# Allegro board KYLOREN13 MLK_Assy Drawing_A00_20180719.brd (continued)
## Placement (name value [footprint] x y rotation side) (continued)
PR4818  5K11R2F-L1-GP  [R402H16]  59.05 70.76 90 top
PR4821  100KR2F-L1-GP  [R402H16]  53.34 82.95 0 top
PR4822  100KR2F-L1-GP  [R402H16]  51.44 82.7 180 top
PR4823  100KR2F-L1-GP  [R402H16]  47.62 75.46 180 top
PR4824  100KR2F-L1-GP  [R402H16]  47.62 79.39 0 top
PR5001  2D2R3-1-U-GP  [R603H22]  152.15 105.81 180 bottom
PR5003  3K65R2F-1-GP  [R402H16]  39.88 78.25 0 top
PR5004  0R0402-PAD-1-GP  [0R0402-PAD]  40.39 79.52 90 top
PR5101  20KR2F-L-GP  [R402H16]  153.34 21.56 90 bottom
PR5102  0R0603-PAD-1-GP-U  [0R0603-PAD-U]  154.43 26.82 0 top
PR5103  0R2J-L-GP  [R402H15]  156.84 21.99 0 bottom
PR5104  100KR2J-1-GP  [R402H16]  156.21 23.51 90 top
PR5105  1MR2J-1-GP  [R402H16]  157.61 21.99 180 bottom
PR5106  0R2J-L-GP  [R402H15]  156.08 21.1 0 bottom
PR5107  20KR2F-L-GP  [R402H16]  155.32 21.1 0 bottom
PR5114  0R0402-PAD-1-GP  [0R0402-PAD]  49.81 24.38 270 top
PR5118  0R0402-PAD-1-GP  [0R0402-PAD]  49.81 23.59 270 top
PR5125  0R0402-PAD-1-GP  [0R0402-PAD]  49.81 25.16 270 top
PR5126  0R2J-L-GP  [R402H15]  49.81 25.93 270 top
PR5127  0R0805-PAD-1-GP-U  [0R0805-PAD-U]  45.52 28.39 270 bottom
PR5201  88K7R2F-GP  [R402H16]  177.8 54.12 270 bottom
PR5202  3K16R2F-GP  [R402H16]  180.85 54.88 0 bottom
PR5203  100KR2F-L1-GP  [R402H16]  181.86 56.15 270 bottom
PR5204  10KR2F-2-DL-GP  [R402H16]  180.09 54.76 180 bottom
PR5208  100KR2J-1-GP  [R402H16]  180.59 59.33 90 bottom
PR5209  0R0402-PAD-1-GP  [0R0402-PAD]  180.59 58.57 90 bottom
PR5210  47KR2J-2-GP  [R402H16]  180.59 57.8 90 bottom
PR5301  47KR2J-2-GP  [R402H16]  37.21 23.26 90 bottom
PR5302  100KR2F-L1-GP  [R402H16]  37.03 18.08 270 bottom
PR5303  16K9R2F-GP  [R402H16]  46.99 19.2 0 bottom
PR5304  13K3R2F-L1-GP  [R402H16]  47.37 20.47 90 bottom
PR5306  0R0402-PAD-1-GP  [0R0402-PAD]  37.21 24.02 270 bottom
PR5308  0R0402-PAD-1-GP  [0R0402-PAD]  37.03 17.29 270 bottom
PR5309  47KR2J-2-GP  [R402H16]  129.16 15.51 180 bottom
PR5310  10KR2F-2-DL-GP  [R402H16]  140.21 21.48 270 bottom
PR5317  0R0402-PAD-1-GP  [0R0402-PAD]  128.4 15.51 0 bottom
PR5319  29K4R2F-GP  [R402H16]  137.03 28.85 180 bottom
PR5320  13K7R2F-GP  [R402H16]  136.27 28.85 0 bottom
PR5321  0R0805-PAD-1-GP-U  [0R0805-PAD-U]  137.41 30.75 90 bottom
PR5322  0R0805-PAD-1-GP-U  [0R0805-PAD-U]  48.51 16.91 180 bottom
PT4701  SE330U2VDM-4-GP  [CT7343H83]  74.3 62.76 180 bottom
PT4702  ST33U25VDM-5-GP  [CT7343H79]  62.48 67.07 270 bottom
PT4801  SE330U2VDM-4-GP  [CT7343H83]  74.22 84.3 0 bottom
PT4803  SE330U2VDM-4-GP  [CT7343H83]  74.22 76.17 180 bottom
PT4805  SE33U25VM-11-GP  [CT7343H83]  54.1 55.64 270 bottom
PT4807  ST33U25VDM-5-GP  [CT7343H79]  52.83 78.12 90 bottom
PU4301  AON7403-GP-U  [PPAK-8P-3232H36]  32.38 73.04 0 bottom
PU4302  AON7403-GP-U  [PPAK-8P-3232H36]  32.38 70.25 180 bottom
PU4401  ISL9538HRTZ-GP-U  [QFN32J4-G2D85H34]  35.05 46.25 270 top
PU4403  AON7380-GP  [PPAK-8P-3232H36]  40.64 61.99 90 top
PU4404  AON7380-GP  [PPAK-8P-3232H36]  41.4 58.69 0 top
PU4405  AON7380-GP  [PPAK-8P-3232H36]  48.9 57.93 270 top
PU4406  AON7380-GP  [PPAK-8P-3232H36]  48.13 61.23 180 top
PU4412  AON7401-GP  [PPAK-8P-3232H36]  146.05 17.54 90 bottom
PU4501  SY8286BRAC-GP  [QFN20Z3-G1D1H36]  126.47 21.23 180 bottom
PU4502  SY8288CRAC-GP  [QFN20Z3-G1D1H36]  63.5 20.85 0 bottom
PU4601  ISL95859CHRTZ-T-1-GP  [QFN40J5-G3D6-DIFF-H34]  44.58 75.96 90 bottom
PU4701  AOZ5038QI-05-GP  [QFN31G5-G4P-9H34]  60.2 61.74 270 bottom
PU4801  AOZ5038QI-05-GP  [QFN31G5-G4P-9H34]  60.2 82.31 270 bottom
PU4802  AOZ5038QI-05-GP  [QFN31G5-G4P-9H34]  60.2 73.17 270 bottom
PU5001  ISL95808HRZ-T-1-GP  [DFN8G2-G1710-U1H40]  151.38 102.63 90 bottom
PU5002  AON7408-GP  [PPAK-8P-3232H36]  143.89 106.7 90 bottom
PU5003  AON7408-GP  [PPAK-8P-3232H36]  142.62 102.89 270 bottom
PU5101  SY8288RAC-GP  [QFN20Z3-G1H36]  154.56 25.04 180 bottom
PU5102  APL5338XAI-TRG-GP  [MSOP10-G2D5H44]  45.54 25.62 90 bottom
PU5201  AOZ2262QI-10-GP-U  [QFN22G4-G2PH42]  176.28 56.91 90 bottom
PU5301  APL5934KAI-TRG-GP-U  [SOIC8-G3530H63]  42.67 18.81 270 bottom
PU5303  APL5934KAI-TRG-GP-U  [SOIC8-G3530H63]  136.14 24.41 0 bottom
Q401  2N7002KDW-1-GP  [SOT-363H44]  160.53 86.51 180 bottom
Q501  PJA138KA-GP  [SOT23DGS2D4H44]  85.47 61.36 0 bottom
Q502  2N7002K-2-GP  [SOT23DGS2D4H44]  85.6 57.93 0 bottom
Q1701  PJT138KA-GP  [SOT-363H44]  144.4 51.33 90 bottom
Q1702  2N7002KDW-1-GP  [SOT-363H44]  132.53 51.74 270 bottom
Q1802  2N7002K-2-GP  [SOT23DGS2D4H44]  156.31 47.9 270 bottom
Q2001  PJT138KA-GP  [SOT-363H44]  183.77 48.91 0 top
Q2408  2N7002K-2-GP  [SOT23DGS2D4H44]  104.9 14.88 0 bottom
Q2414  2N7002K-2-GP  [SOT23DGS2D4H44]  68.17 14.62 270 bottom
Q2416  2N7002KDW-1-GP  [SOT-363H44]  124.97 11.04 270 bottom
Q2417  2N7002KDW-1-GP  [SOT-363H44]  107.82 11.45 180 bottom
Q2505  2N7002K-2-GP  [SOT23DGS2D4H44]  150.93 77.23 270 bottom
Q2507  PJA3415-GP  [SOT23DGS2D4H44]  155.07 52.09 180 bottom
Q2510  2N7002K-2-GP  [SOT23DGS2D4H44]  151.51 52.09 180 bottom
Q2601  2N7002KDW-1-GP  [SOT-363H44]  46.23 13.48 270 bottom
Q2602  2N7002K-2-GP  [SOT23DGS2D4H44]  145.54 97.81 180 bottom
Q2603  MMBT3904-5-GP-U  [SOT23CBE2D4H46-U]  48.77 68.73 180 bottom
Q4001  2N7002K-2-GP  [SOT23DGS2D4H44]  33.86 18.71 180 bottom
Q4002  PJA3415-GP  [SOT23DGS2D4H44]  30.12 20.39 0 bottom
Q4301  PJA138KA-GP  [SOT23DGS2D4H44]  53.95 13.58 180 bottom
Q4302  MMBT3904-5-GP-U  [SOT23CBE2D4H46-U]  57.43 13.78 180 bottom
Q4304  LMUN5212T1G-GP  [SOT323CBE2D2H40]  35.69 80.66 180 bottom
Q4305  LTA024EUB-FS8-GP  [SC70-2D2-312H44]  33.15 80.66 180 bottom
Q4348  PJA3415-GP  [SOT23DGS2D4H44]  31.65 25.52 90 bottom
Q4349  2N7002KDW-1-GP  [SOT-363H44]  28.52 25.16 180 bottom
Q5705  2N7002KDW-1-GP  [SOT-363H44]  15.88 59.45 180 bottom
Q6101  PJA3415-GP  [SOT23DGS2D4H44]  182.63 41.67 180 top
Q6102  2N7002K-2-GP  [SOT23DGS2D4H44]  182.63 44.21 180 top
Q6401  RN2418-GP  [SOT23CBE2D6H62]  116.71 15.13 270 bottom
Q6402  RN2418-GP  [SOT23CBE2D6H62]  120.02 15.13 270 bottom
Q6403  PJA138KA-GP  [SOT23DGS2D4H44]  123.95 14.75 0 bottom
Q6404  PJT138KA-GP  [SOT-363H44]  121.46 10.91 90 bottom
Q6501  PJA3402-R1-00001-GP  [SOT23DGS2D4H44]  74.8 15.89 180 bottom
Q6502  PJA3415-GP  [SOT23DGS2D4H44]  128.27 9.7 0 bottom
Q6503  2N7002K-2-GP  [SOT23DGS2D4H44]  131.7 9.7 0 bottom
Q6504  2N7002KDW-1-GP  [SOT-363H44]  139.45 11.07 270 bottom
Q6505  RN2418-GP  [SOT23CBE2D6H62]  64.9 13.61 270 bottom
Q7401  PJA3415-GP  [SOT23DGS2D4H44]  21.97 65.8 0 bottom
Q7402  PJT138KA-GP  [SOT-363H44]  18.8 66.31 270 bottom
Q7404  2N7002KDW-1-GP  [SOT-363H44]  17.65 69.74 0 bottom
Q7405  2N7002KDW-1-GP  [SOT-363H44]  20.19 69.74 0 bottom
Q7406  PJT138KA-GP  [SOT-363H44]  15.11 68.73 0 bottom
R301  1KR2J-1-GP  [R402H16]  95 95.9 0 bottom
R302  499R2F-2-GP  [R402H16]  96.27 96.28 270 bottom
R303  100KR2J-1-GP  [R402H16]  130.68 61.54 90 bottom
R304  49D9R2F-GP  [R402H16]  124.33 73.04 180 top
R305  49D9R2F-GP  [R402H16]  126.69 74.47 270 top
R308  1KR2J-1-GP  [R402H16]  115.32 95.4 270 bottom
R310  51R2J-2-GP  [R402H16]  94.58 94.11 0 bottom
R317  51R2J-2-GP  [R402H16]  96.39 88.13 270 top
R401  24D9R2F-L-GP  [R402H16]  108.5 85.24 90 top
R402  10KR2J-3-GP  [R402H16]  149.86 90.44 270 top
R403  100KR2J-1-GP  [R402H16]  131.67 86.41 0 top
R404  0R2J-L-GP  [R402H15]  161.04 88.54 90 bottom
R405  10KR2J-3-GP  [R402H16]  162.31 86.51 0 bottom
R406  10KR2J-3-GP  [R402H16]  160.4 84.47 90 bottom
R501  121R2F-GP  [R402H16]  123.72 74.68 180 top
R502  80D6R2F-L-GP  [R402H16]  122.95 74.68 180 top
R503  100R2F-L1-GP-U  [R402H14]  122.19 74.68 180 top
R504  0R0402-PAD-2-GP  [0R0402-PAD-1]  135.2 57.73 90 top
R505  470R2F-GP  [R402H16]  134.62 56.41 180 top
R506  10KR2F-2-DL-GP  [R402H16]  84.07 59.96 270 bottom
R507  10KR2F-2-DL-GP  [R402H16]  83.31 58.31 180 bottom
R601  49D9R2F-GP  [R402H16]  103.4 88.69 0 top
R709  0R0402-PAD-2-GP  [0R0402-PAD-1]  91.82 96.28 90 bottom
R719  100R2F-L1-GP-U  [R402H14]  110.94 86.56 270 top
R720  100R2F-L1-GP-U  [R402H14]  110.79 87.91 270 top
R723  54D9R2F-L1-GP  [R402H16]  88.77 95.14 90 bottom
R726  100R2F-L1-GP-U  [R402H14]  91.82 97.05 270 bottom
R727  56R2F-1-GP  [R402H16]  89.53 96.79 90 bottom
R728  220R2F-GP  [R402H16]  90.04 97.55 90 bottom
R732  0R0402-PAD-2-GP  [0R0402-PAD-1]  88.27 96.41 180 bottom
R807  100R2F-L1-GP-U  [R402H14]  94.61 88.28 270 top
R808  100R2F-L1-GP-U  [R402H14]  92.96 88.28 90 top
R809  100R2F-L1-GP-U  [R402H14]  117.52 86.51 270 top
R810  100R2F-L1-GP-U  [R402H14]  118.92 85.24 270 top
R811  D0002R5J-2-GP  [R805H16]  105.54 82.82 270 top
R812  D0002R5J-2-GP  [R805H16]  102.36 82.82 270 top
R813  D0002R5J-2-GP  [R805H16]  105.54 80.92 270 top
R814  D0002R5J-2-GP  [R805H16]  105.54 79.01 270 top
R815  D0002R5J-2-GP  [R805H16]  102.36 80.92 270 top
R1103  0R0603-PAD-2-GP-U  [0R0603-PAD-1-U]  137.08 75.44 270 top
R1104  0R0603-PAD-2-GP-U  [0R0603-PAD-1-U]  150.41 77.62 270 top
R1201  240R2D-GP  [R402H16]  50.23 41.17 270 top
R1202  2D7R2F-1-GP  [R402H16]  94.66 34.95 90 top
R1203  24D9R2F-L-GP  [R402H16]  92.5 34.19 270 top
R1204  240R2D-GP  [R402H16]  59.73 41.17 270 top
R1205  240R2D-GP  [R402H16]  80.03 41.17 270 top
R1208  49D9R2F-GP  [R402H16]  52.11 33.68 90 top
R1211  36R2F-1-GP  [R402H16]  44.49 38.89 270 top
R1212  240R2F-1-GP  [R402H16]  50.68 42.4 180 top
R1213  240R2F-1-GP  [R402H16]  60.18 42.4 180 top
R1214  240R2F-1-GP  [R402H16]  80.48 42.4 180 top
R1215  240R2F-1-GP  [R402H16]  70.33 42.4 180 top
R1220  0R2J-L-GP  [R402H15]  93.13 38.13 180 bottom
R1221  0R2J-L-GP  [R402H15]  91.57 37.1 0 bottom
R1222  1K8R2F-GP  [R402H16]  92.63 35.46 0 top
R1223  1K8R2F-GP  [R402H16]  93.39 35.46 0 top
R1224  36R2F-1-GP  [R402H16]  47.92 36.47 270 top
R1225  33R2F-3-GP  [R402H16]  47.92 39.78 270 top
R1226  33R2F-3-GP  [R402H16]  47.92 40.54 270 top
R1234  240R2D-GP  [R402H16]  69.88 41.17 270 top
R1301  240R2D-GP  [R402H16]  101.64 40.79 180 bottom
R1302  2D7R2F-1-GP  [R402H16]  99.68 33.78 270 top
R1303  24D9R2F-L-GP  [R402H16]  100.46 35.32 180 top
R1304  240R2D-GP  [R402H16]  112.22 41.17 270 top
R1305  240R2D-GP  [R402H16]  122.37 41.15 270 top
R1306  240R2D-GP  [R402H16]  132.52 41.17 270 top
R1311  36R2F-1-GP  [R402H16]  145.92 39.64 270 top
R1312  36R2F-1-GP  [R402H16]  145.46 37.24 270 bottom
R1313  33R2F-3-GP  [R402H16]  145.38 41.03 270 bottom
R1314  33R2F-3-GP  [R402H16]  145.38 41.82 270 bottom
R1320  1K8R2F-GP  [R402H16]  99.68 32.26 90 top
R1321  1K8R2F-GP  [R402H16]  99.68 33.02 90 top
R1330  49D9R2F-GP  [R402H16]  135.25 34.06 0 top
R1331  240R2F-1-GP  [R402H16]  101.64 42.57 0 bottom
R1332  240R2F-1-GP  [R402H16]  113.32 42.4 180 top
R1333  240R2F-1-GP  [R402H16]  123.47 42.38 180 top
R1334  240R2F-1-GP  [R402H16]  133.61 42.4 180 top
R1339  0R2J-L-GP  [R402H15]  101.6 37.86 180 bottom
R1340  0R2J-L-GP  [R402H15]  143.76 37.99 90 top
R1501  20KR2J-L2-GP  [R402H16]  150.37 59.45 180 bottom
R1502  1KR2J-1-GP  [R402H16]  140.97 75.33 270 bottom
R1503  1KR2J-1-GP  [R402H16]  142.75 74.57 270 bottom
R1504  4K7R2J-2-GP  [R402H16]  134.75 80.41 0 top
R1505  20KR2J-L2-GP  [R402H16]  133.41 79.86 270 top
R1506  100KR2F-L1-GP  [R402H16]  132.23 63.48 0 bottom
R1507  1KR2J-1-GP  [R402H16]  133.01 63.48 180 bottom
R1508  100KR2F-L1-GP  [R402H16]  137.03 62.5 90 bottom
R1509  4K7R2J-2-GP  [R402H16]  137.03 63.39 270 bottom
R1510  100KR2F-L1-GP  [R402H16]  140.59 60.72 90 top
R1511  4K7R2J-2-GP  [R402H16]  142.24 60.72 90 top
R1512  4K7R2J-2-GP  [R402H16]  120.9 60.09 0 bottom
R1515  20KR2J-L2-GP  [R402H16]  150.5 58.06 90 top
R1516  4K7R2J-2-GP  [R402H16]  151.76 57.04 0 top
R1517  1KR2J-1-GP  [R402H16]  93.82 94.11 0 bottom
R1518  1KR2J-1-GP  [R402H16]  87.12 90.7 180 bottom
R1519  4K7R2J-2-GP  [R402H16]  149.86 70.5 0 top
R1520  4K7R2J-2-GP  [R402H16]  149.73 72.28 270 top
R1521  10KR2J-3-GP  [R402H16]  150.88 75.08 270 bottom
R1522  4K7R2J-2-GP  [R402H16]  138.46 76.93 180 top
R1523  20KR2J-L2-GP  [R402H16]  139.24 76.93 0 top
R1524  100KR2F-L1-GP  [R402H16]  139.06 55.01 180 top
R1525  20KR2J-L2-GP  [R402H16]  136.91 56.66 0 top
R1526  4K7R2J-2-GP  [R402H16]  153.97 71.16 180 top
R1527  1KR2J-1-GP  [R402H16]  140.97 73.55 270 bottom
R1528  4K7R2J-2-GP  [R402H16]  153.97 69.56 180 top
R1551  4K7R2J-2-GP  [R402H16]  135.51 80.41 0 top
R1552  20KR2J-L2-GP  [R402H16]  153.67 81.17 180 top
R1553  20KR2J-L2-GP  [R402H16]  150.5 61.23 180 top
R1554  20KR2J-L2-GP  [R402H16]  149.61 74.82 0 bottom
R1555  20KR2J-L2-GP  [R402H16]  136.4 60.47 270 top
R1601  0R2J-L-GP  [R402H15]  129.03 85.87 180 top
R1602  0R2J-L-GP  [R402H15]  132.72 89.05 90 top
R1603  113R2F-GP  [R402H16]  128.97 87.1 90 top
R1604  100R2F-L1-GP-U  [R402H14]  130.71 87.95 90 top
R1606  10KR2J-3-GP  [R402H16]  149.86 91.33 90 top
R1608  10KR2J-3-GP  [R402H16]  149.86 89.68 90 top
R1701  10KR2J-3-GP  [R402H16]  154.43 88.28 270 top
R1702  1KR2J-1-GP  [R402H16]  129.13 51.84 90 bottom
R1703  10KR2J-3-GP  [R402H16]  125.48 63.26 0 bottom
R1704  0R0402-PAD-2-GP  [0R0402-PAD-1]  130.68 51.77 0 bottom
R1706  0R0402-PAD-2-GP  [0R0402-PAD-1]  123.19 58.82 0 bottom
R1707  10KR2J-3-GP  [R402H16]  125.19 74.07 0 top
R1708  0R2J-L-GP  [R402H15]  127.51 55.52 180 bottom
R1713  0R0402-PAD-2-GP  [0R0402-PAD-1]  137.79 55.21 180 top
R1714  10KR2J-3-GP  [R402H16]  111.89 94.13 270 bottom
R1715  100KR2J-1-GP  [R402H16]  136.55 54.45 270 top
R1716  100KR2F-L1-GP  [R402H16]  159.64 81.3 180 bottom
R1717  10KR2J-3-GP  [R402H16]  160.4 83.33 270 bottom
R1718  100KR2F-L1-GP  [R402H16]  158.62 80.66 0 bottom
R1719  47KR2F-GP  [R402H16]  157.73 80.66 180 bottom
R1721  10KR2J-3-GP  [R402H16]  127 60.22 180 bottom
R1722  10KR2J-3-GP  [R402H16]  127.89 60.22 180 bottom
R1726  10KR2J-3-GP  [R402H16]  141.35 51.83 180 bottom
R1727  100KR2J-1-GP  [R402H16]  146.43 51.45 180 bottom
R1728  0R0402-PAD-2-GP  [0R0402-PAD-1]  147.45 51.45 0 bottom
R1730  330KR2J-L1-GP  [R402H16]  143.89 51.2 180 top
R1731  100KR2F-L1-GP  [R402H16]  128.29 74.78 0 top
R1737  100KR2J-1-GP  [R402H16]  134.41 52.6 180 bottom
R1738  10KR2J-3-GP  [R402H16]  126.75 55.52 0 bottom
R1801  150KR2J-GP  [R402H16]  137.92 59.71 180 top
R1803  60D4R2F-GP  [R402H16]  132.76 94.51 0 bottom
R1805  33R2F-3-GP  [R402H16]  127.25 60.22 0 top
R1815  10MR2J-L-GP  [R402H16]  123.44 58.32 90 top
R1816  10KR2J-3-GP  [R402H16]  158.39 48.76 180 bottom
R1818  8K2R2F-1-GP  [R402H16]  131.57 55.9 90 top
R1820  10KR2J-3-GP  [R402H16]  131.57 56.66 270 top
R1821  10KR2J-3-GP  [R402H16]  128.14 60.22 180 top
R1839  0R2J-L-GP  [R402H15]  135.04 93.83 0 bottom
R1840  0R2J-L-GP  [R402H15]  134.28 93.83 0 bottom
R1841  1MR2J-1-GP  [R402H16]  134.66 95.05 90 bottom
R1901  200R2F-L-GP  [R402H16]  134.24 71.9 180 top
R1908  0R0402-PAD-2-GP  [0R0402-PAD-1]  122.43 60.09 0 bottom
R1909  1KR2J-1-GP  [R402H16]  119.38 60.09 0 bottom
R1910  10KR2J-3-GP  [R402H16]  142.75 72.79 90 bottom
R1911  10KR2J-3-GP  [R402H16]  142.75 73.55 270 bottom
R1920  0R0402-PAD-2-GP  [0R0402-PAD-1]  121.67 60.09 0 bottom
R1921  0R0402-PAD-2-GP  [0R0402-PAD-1]  120.14 60.09 0 bottom
R2001  0R2J-L-GP  [R402H15]  130.53 59.2 180 bottom
R2002  0R2J-L-GP  [R402H15]  131.29 59.2 180 bottom
R2003  10KR2F-2-DL-GP  [R402H16]  183.64 51.58 0 top
R2004  10KR2J-3-GP  [R402H16]  182.47 51.66 270 top
R2005  10KR2J-3-GP  [R402H16]  149.86 87.39 90 top
R2008  10KR2J-3-GP  [R402H16]  152.4 86.76 90 top
R2009  10KR2J-3-GP  [R402H16]  149.37 84.99 0 top
R2010  10KR2J-3-GP  [R402H16]  150.16 84.99 180 top
R2011  10KR2J-3-GP  [R402H16]  148.21 73.81 90 bottom
R2012  10KR2J-3-GP  [R402H16]  145.08 73.03 90 bottom
R2013  10KR2J-3-GP  [R402H16]  148.56 71.96 90 bottom
R2014  10KR2J-3-GP  [R402H16]  146.88 71.96 90 bottom
R2015  10KR2J-3-GP  [R402H16]  145.1 76.18 90 bottom
R2016  10KR2J-3-GP  [R402H16]  148.21 76.85 90 bottom
R2017  10KR2J-3-GP  [R402H16]  145.1 75.39 90 bottom
R2018  10KR2J-3-GP  [R402H16]  148.21 76.09 90 bottom
R2020  0R2J-L-GP  [R402H15]  150.11 79.52 90 top
R2021  0R2J-L-GP  [R402H15]  150.11 78.76 90 top
R2022  10KR2J-3-GP  [R402H16]  145.1 74.6 90 bottom
R2027  0R2J-L-GP  [R402H15]  147.32 58.69 180 top
R2028  0R2J-L-GP  [R402H15]  129.7 54.57 270 bottom
R2029  10KR2J-3-GP  [R402H16]  148.21 75.33 90 bottom
R2030  10KR2J-3-GP  [R402H16]  146.81 72.92 90 bottom
R2031  10KR2J-3-GP  [R402H16]  148.59 72.92 90 bottom
R2032  10KR2J-3-GP  [R402H16]  145.1 73.79 90 bottom
R2033  10KR2J-3-GP  [R402H16]  148.21 74.57 90 bottom
R2034  10KR2J-3-GP  [R402H16]  149.35 74.69 180 top
R2035  10KR2J-3-GP  [R402H16]  150.11 74.69 0 top
R2037  10KR2J-3-GP  [R402H16]  142.75 75.33 270 bottom
R2038  10KR2J-3-GP  [R402H16]  151.64 74.69 0 top
R2041  10KR2J-3-GP  [R402H16]  137.23 82.6 90 top
R2043  10KR2J-3-GP  [R402H16]  131.55 57.5 270 top
R2044  10KR2J-3-GP  [R402H16]  139.32 83.58 0 top
R2045  10KR2J-3-GP  [R402H16]  149.86 86.25 270 top
R2046  10KR2J-3-GP  [R402H16]  150.88 74.69 0 top
R2048  51KR2J-1-GP  [R402H16]  151.64 83.89 90 top
R2049  51KR2J-1-GP  [R402H16]  152.4 74.69 0 top
R2050  10KR2J-3-GP  [R402H16]  185.04 47.01 270 top
R2051  10KR2J-3-GP  [R402H16]  129.13 52.97 90 bottom
R2052  10KR2J-3-GP  [R402H16]  129.7 53.79 90 bottom
R2053  10KR2J-3-GP  [R402H16]  133.46 57.78 90 top
R2101  150R2F-1-GP  [R402H16]  135.58 72.24 90 top
R2102  0R2J-L-GP  [R402H15]  160.78 96.16 0 top
R2107  10KR2J-3-GP  [R402H16]  137.66 76.94 0 top
R2108  200R2F-L-GP  [R402H16]  133.39 80.8 270 top
R2109  10KR2J-3-GP  [R402H16]  151.66 85.42 90 top
R2110  10KR2J-3-GP  [R402H16]  151.66 84.66 90 top
R2111  10KR2J-3-GP  [R402H16]  155.06 80.65 90 bottom
R2112  10KR2J-3-GP  [R402H16]  155.06 81.56 270 bottom
R2113  10KR2J-3-GP  [R402H16]  134.92 76.35 270 top
R2114  10KR2J-3-GP  [R402H16]  134.92 75.57 270 top
R2115  10KR2J-3-GP  [R402H16]  155.57 79.22 90 bottom
R2116  10KR2J-3-GP  [R402H16]  157.35 79.21 270 bottom
R2117  10KR2J-3-GP  [R402H16]  130.98 79.5 90 top
R2118  10KR2J-3-GP  [R402H16]  130.88 81.66 180 top
R2119  0R0402-PAD-2-GP  [0R0402-PAD-1]  140.97 72.79 270 bottom
R2202  0R0603-PAD-2-GP-U  [0R0603-PAD-1-U]  142.49 97.3 90 bottom
R2203  0R0603-PAD-2-GP-U  [0R0603-PAD-1-U]  151.51 81.3 180 top
R2204  0R0603-PAD-2-GP-U  [0R0603-PAD-1-U]  148.72 59.07 180 top
R2205  0R0603-PAD-2-GP-U  [0R0603-PAD-1-U]  124.89 98.44 270 bottom
R2401  0R0402-PAD-2-GP  [0R0402-PAD-1]  19.41 31.79 270 bottom
R2402  0R0402-PAD-2-GP  [0R0402-PAD-1]  104.39 9.67 90 bottom
R2403  0R2J-L-GP  [R402H15]  106.55 17.67 180 bottom
R2404  0R2J-L-GP  [R402H15]  108.23 8.6 270 bottom
R2405  0R2J-L-GP  [R402H15]  186.33 43.6 0 top
R2406  10KR2J-3-GP  [R402H16]  108.23 7.84 270 bottom
R2407  100KR2J-1-GP  [R402H16]  82.37 9.37 0 bottom
R2410  0R2J-L-GP  [R402H15]  95.12 23.13 90 bottom
R2414  10KR2J-3-GP  [R402H16]  96.39 4.72 90 top
R2415  10KR2J-3-GP  [R402H16]  87.12 19.8 90 top
R2416  10KR2J-3-GP  [R402H16]  20.83 32.53 0 bottom
R2417  100KR2J-1-GP  [R402H16]  102.23 14.62 270 bottom
R2418  0R2J-L-GP  [R402H15]  102.23 15.39 270 bottom
R2421  330R2J-3-GP  [R402H16]  90.55 5.35 270 top
R2423  330R2J-3-GP  [R402H16]  90.07 6.52 180 top
R2424  20KR2F-L-GP  [R402H16]  83.95 16.91 90 top
R2430  10KR2J-3-GP  [R402H16]  87.88 24.02 90 bottom
R2432  1KR2J-1-GP  [R402H16]  84.45 6.62 0 top
R2434  100KR2J-1-GP  [R402H16]  80.64 12.85 90 top
R2437  43R2J-GP  [R402H16]  104.39 10.43 270 bottom
R2440  0R0402-PAD-2-GP  [0R0402-PAD-1]  103.25 17.67 180 bottom
R2441  100KR2F-L1-GP  [R402H16]  94.61 6.24 270 top
R2442  27KR2F-L-GP  [R402H16]  96.39 6.24 270 top
R2443  37K4R2F-1-GP  [R402H16]  92.94 5.48 270 top
R2444  100KR2F-L1-GP  [R402H16]  92.94 6.24 90 top
R2445  0R0402-PAD-2-GP  [0R0402-PAD-1]  92.2 8.78 270 top
R2446  0R0603-PAD-2-GP-U  [0R0603-PAD-1-U]  80.77 13.99 90 top
R2447  0R0402-PAD-2-GP  [0R0402-PAD-1]  80.26 12.46 90 bottom
R2448  10KR2F-2-DL-GP  [R402H16]  84.33 18.18 180 top
R2451  100KR2J-1-GP  [R402H16]  85.22 6.62 180 top
R2452  100KR2J-1-GP  [R402H16]  63.12 3.37 0 top
R2453  100KR2J-1-GP  [R402H16]  64.14 3.37 0 top
R2454  100KR2J-1-GP  [R402H16]  88.11 6.24 90 top
R2455  100KR2J-1-GP  [R402H16]  105.03 17.67 180 bottom
R2456  100KR2J-1-GP  [R402H16]  96.39 23.54 0 bottom
R2459  0R0402-PAD-2-GP  [0R0402-PAD-1]  80.26 13.23 90 bottom
R2461  0R2J-L-GP  [R402H15]  82.04 5.61 270 bottom
R2462  0R0402-PAD-2-GP  [0R0402-PAD-1]  95.12 23.89 90 bottom
R2463  1KR2J-1-GP  [R402H16]  88.11 7 270 top
R2465  10KR2F-2-DL-GP  [R402H16]  83.69 19.96 90 top
R2467  0R0402-PAD-2-GP  [0R0402-PAD-1]  105.28 11.96 0 bottom
R2468  0R0402-PAD-2-GP  [0R0402-PAD-1]  109.55 12.57 180 bottom
R2472  0R2J-L-GP  [R402H15]  88.49 7.89 90 top
R2473  0R0402-PAD-2-GP  [0R0402-PAD-1]  88.01 8.65 90 top
R2480  100KR2J-1-GP  [R402H16]  99.34 13.2 270 top
R2489  100KR2J-1-GP  [R402H16]  68.2 11.45 180 bottom
R2494  0R2J-L-GP  [R402H15]  92.58 4.21 0 top
R2495  0R2J-L-GP  [R402H15]  124.71 12.72 90 bottom
R2496  100KR2J-1-GP  [R402H16]  90.35 25.55 270 bottom
R2497  100KR2J-1-GP  [R402H16]  86.23 8.65 90 top
R2498  0R2J-L-GP  [R402H15]  124.71 9.16 90 bottom
R2503  15R2F-2-GP  [R402H16]  141.48 59.96 270 top
R2504  10MR2J-L-GP  [R402H16]  152.78 75.33 90 bottom
R2505  0R2J-L-GP  [R402H15]  156.97 76.22 90 bottom
R2506  33R2F-3-GP  [R402H16]  134.61 57.99 270 bottom
R2507  33R2F-3-GP  [R402H16]  137.16 59.94 180 bottom
R2508  33R2F-3-GP  [R402H16]  135.89 60.57 0 bottom
R2509  33R2F-3-GP  [R402H16]  133.8 63.48 0 bottom
R2511  4K7R2J-2-GP  [R402H16]  151.26 54.63 0 bottom
R2512  0R2J-L-GP  [R402H15]  153.16 53.61 270 bottom
R2513  0R2J-L-GP  [R402H15]  160.55 74.54 90 bottom
R2514  10KR2J-3-GP  [R402H16]  155.91 73.54 0 bottom
R2516  0R0603-PAD-2-GP-U  [0R0603-PAD-1-U]  151.05 73.26 0 bottom
R2517  47KR2F-GP  [R402H16]  156.97 75.33 270 bottom
R2518  100KR2J-1-GP  [R402H16]  159.66 49.22 270 bottom
R2519  4K7R2J-2-GP  [R402H16]  139.19 62.12 180 bottom
R2520  100KR2J-1-GP  [R402H16]  156.67 73.54 0 bottom
R2522  0R5J-5-GP  [R805H24]  156.34 71.14 180 bottom
R2567  1MR2J-1-GP  [R402H16]  160.22 50.49 0 bottom
R2601  0R2J-L-GP  [R402H15]  147.32 97.68 90 top
R2602  0R0402-PAD-2-GP  [0R0402-PAD-1]  148.59 97.3 0 top
R2603  7K5R2F-1-GP  [R402H16]  151.26 49.29 270 bottom
R2604  7K5R2F-1-GP  [R402H16]  145.54 98.19 90 top
R2607  10KR2J-3-GP  [R402H16]  155.7 98.19 0 top
R2608  27KR2F-L-GP  [R402H16]  62.36 55.39 270 bottom
R2609  10R2F-L-GP  [R402H14]  93.34 4.21 0 top
R2610  NTC-100K-8-GP  [NTC-603H38]  63.5 56.53 270 bottom
R2611  0R0402-PAD-2-GP  [0R0402-PAD-1]  92.58 2.43 180 top
R2612  0R0402-PAD-2-GP  [0R0402-PAD-1]  169.8 83.08 180 bottom
R2613  0R0402-PAD-2-GP  [0R0402-PAD-1]  165.28 80.31 270 bottom
R2614  0R0402-PAD-2-GP  [0R0402-PAD-1]  165.28 79.55 270 bottom
R2615  0R2J-L-GP  [R402H15]  149.35 97.3 0 top
R2616  0R2J-L-GP  [R402H15]  151.26 96.41 270 top
R2705  0R0603-PAD-2-GP-U  [0R0603-PAD-1-U]  20.85 11.45 0 top
R2707  0R0805-PAD-2-GP-U  [0R0805-PAD-1-U]  25.15 11.07 180 top
R2712  0R0805-PAD-2-GP-U  [0R0805-PAD-1-U]  23.33 11.05 180 top
R2721  0R0402-PAD-2-GP  [0R0402-PAD-1]  29.46 18.05 270 top
R2724  0R0603-PAD-2-GP-U  [0R0603-PAD-1-U]  21.97 25.42 0 top
R2728  0R2J-L-GP  [R402H15]  17.4 18.18 90 top
R2730  33R2F-3-GP  [R402H16]  26.19 24.91 0 top
R2738  0R0402-PAD-2-GP  [0R0402-PAD-1]  29.46 17.16 270 top
R2739  0R0805-PAD-2-GP-U  [0R0805-PAD-1-U]  21.84 15.89 0 bottom
R2741  200KR2F-L-GP  [R402H16]  29.59 12.97 90 top
R2742  100KR2J-1-GP  [R402H16]  32 14.24 0 top
R2743  10KR2J-3-GP  [R402H16]  30.73 15.39 0 top
R2744  100KR2J-1-GP  [R402H16]  27.81 13.23 180 top
R2745  2K2R2J-2-GP  [R402H16]  9.4 7.26 180 bottom
R2746  0R2J-L-GP  [R402H15]  28.7 24.53 0 top
R2747  100KR2J-1-GP  [R402H16]  19.56 12.72 0 top
R2748  0R3J-0-U-GP  [R603H22]  26.04 18.56 180 bottom
R2749  0R0603-PAD-2-GP-U  [0R0603-PAD-1-U]  32 16.4 0 top
R2750  0R3J-0-U-GP  [R603H22]  26.04 20.97 0 bottom
R2751  0R0603-PAD-2-GP-U  [0R0603-PAD-1-U]  23.62 27.58 0 top
R2754  0R0402-PAD-2-GP  [0R0402-PAD-1]  17.4 17.42 90 top
R2905  0R0402-PAD-2-GP  [0R0402-PAD-1]  17.53 26.56 180 top
R2907  0R0402-PAD-2-GP  [0R0402-PAD-1]  17.4 21.23 270 top
R2908  0R0402-PAD-2-GP  [0R0402-PAD-1]  5.21 13.73 270 bottom
R2909  0R0402-PAD-2-GP  [0R0402-PAD-1]  17.4 22.5 270 top
R2910  0R0402-PAD-2-GP  [0R0402-PAD-1]  16.76 26.05 270 bottom
R2911  10R2F-L-GP  [R402H14]  15.37 22.5 0 bottom
R2912  10R2F-L-GP  [R402H14]  17.02 24.78 90 bottom
R2914  0R0402-PAD-2-GP  [0R0402-PAD-1]  16.38 5.86 180 top
R2915  0R2J-L-GP  [R402H15]  15.62 5.86 180 top
R2921  0R0402-PAD-2-GP  [0R0402-PAD-1]  17.48 22.29 0 bottom
R2922  0R0402-PAD-2-GP  [0R0402-PAD-1]  17.22 20.03 0 bottom
R2923  0R0603-PAD-2-GP-U  [0R0603-PAD-1-U]  21.97 25.55 0 bottom
R3402  0R0402-PAD-2-GP  [0R0402-PAD-1]  20.19 38.75 0 bottom
R3403  20KR2F-L-GP  [R402H16]  20.45 47.01 180 bottom
R3404  22K1R2F-L-GP  [R402H16]  21.21 47.01 180 bottom
R3405  0R0402-PAD-2-GP  [0R0402-PAD-1]  22.86 38.75 0 bottom
R3406  0R0402-PAD-2-GP  [0R0402-PAD-1]  20.95 38.75 0 bottom
R3501  0R0402-PAD-2-GP  [0R0402-PAD-1]  20.95 40.79 270 top
R3502  0R0402-PAD-2-GP  [0R0402-PAD-1]  20.95 41.55 270 top
R3503  0R0402-PAD-2-GP  [0R0402-PAD-1]  22.73 38.75 270 top
R3504  0R0402-PAD-2-GP  [0R0402-PAD-1]  22.73 39.52 270 top
R4002  0R0402-PAD-2-GP  [0R0402-PAD-1]  161.62 78.2 270 bottom
R4004  10KR2J-3-GP  [R402H16]  157.02 63.39 90 bottom
R4005  1KR2J-1-GP  [R402H16]  160.27 78.38 180 bottom
R4006  20KR2F-L-GP  [R402H16]  106.93 20.19 0 bottom
R4009  10KR2J-3-GP  [R402H16]  101.47 21.1 90 bottom
R4010  0R0402-PAD-2-GP  [0R0402-PAD-1]  105.16 21.35 0 bottom
R4011  0R0402-PAD-2-GP  [0R0402-PAD-1]  161.62 79.01 90 bottom
R4014  0R2J-L-GP  [R402H15]  105.66 19.07 90 bottom
R4018  0R2J-L-GP  [R402H15]  158.88 61.36 0 bottom
R4024  0R0402-PAD-2-GP  [0R0402-PAD-1]  149.61 93.24 270 top
R4029  0R0402-PAD-2-GP  [0R0402-PAD-1]  164.08 75.84 90 bottom
R4030  0R0402-PAD-2-GP  [0R0402-PAD-1]  164.13 76.73 90 bottom
R4031  100KR2J-1-GP  [R402H16]  162.05 75.71 0 bottom
R4032  100KR2J-1-GP  [R402H16]  160.4 76.73 180 bottom
R4033  0R2J-L-GP  [R402H15]  164.13 77.51 90 bottom
R4034  10KR2J-3-GP  [R402H16]  32 23.26 270 bottom
R4035  20KR2J-L2-GP  [R402H16]  29.59 22.47 270 bottom
R4036  0R0603-PAD-2-GP-U  [0R0603-PAD-1-U]  150.75 99.21 270 top
R4038  0R2J-L-GP  [R402H15]  150.37 61.23 180 bottom
R4039  0R0402-PAD-2-GP  [0R0402-PAD-1]  155.32 63.39 90 bottom
R4040  0R2J-L-GP  [R402H15]  155.83 58.82 0 bottom
R4042  20KR2J-L2-GP  [R402H16]  156.59 58.82 0 bottom
R4043  0R0603-PAD-2-GP-U  [0R0603-PAD-1-U]  160.66 63.9 270 bottom
R4045  0R6J-L-GP  [R1206H26]  154.43 65.17 90 bottom
R4301  0R0402-PAD-2-GP  [0R0402-PAD-1]  167 12.08 270 top
R4302  15KR2F-GP  [R402H16]  56.13 12.97 270 top
R4303  100KR2J-1-GP  [R402H16]  36.2 77.74 90 bottom
R4304  2K2R2J-2-GP  [R402H16]  51.87 14.98 90 bottom
R4305  33R2J-2-GP  [R402H16]  51.61 14.29 270 top
R4306  33R2J-2-GP  [R402H16]  53.47 15.77 270 top
R4307  240KR3-GP  [R603H22]  34.16 76.35 270 bottom
R4308  47KR2F-GP  [R402H16]  35.05 78.63 270 bottom
R4309  100KR2J-1-GP  [R402H16]  55.63 14.24 180 top
R4310  10KR2J-3-GP  [R402H16]  57.91 12.97 270 top
R4311  100KR2F-L1-GP  [R402H16]  35.18 73.3 270 bottom
R4315  18K7R2F-GP  [R402H16]  24.64 25.57 90 bottom
R4316  20KR2J-L2-GP  [R402H16]  29.34 69.61 90 bottom
R4317  0R0603-PAD-2-GP-U  [0R0603-PAD-1-U]  55.37 16.4 0 top
R4318  100KR2J-1-GP  [R402H16]  30.05 28.01 0 bottom
R4327  100R2J-2-GP  [R402H14]  168.15 10.43 0 top
R4333  10KR2F-2-DL-GP  [R402H16]  27.84 28.75 180 bottom
R4368  0R0402-PAD-2-GP  [0R0402-PAD-1]  33.27 24.07 0 bottom
R4369  100KR2F-L1-GP  [R402H16]  26.47 25.19 180 bottom
R4370  100KR2F-L1-GP  [R402H16]  26.44 26.99 180 bottom
R4376  470KR2F-GP  [R402H16]  33.3 58.18 90 top
R4377  84K5R2F-GP  [R402H16]  33.3 59 270 top
R4378  100KR2J-1-GP  [R402H16]  36.88 55.73 180 bottom
R5501  0R0402-PAD-2-GP  [0R0402-PAD-1]  107.95 102.89 180 top
R5502  0R2J-L-GP  [R402H15]  100.66 104.13 90 top
R5503  0R0402-PAD-2-GP  [0R0402-PAD-1]  87.63 103.78 180 top
R5504  100KR2J-1-GP  [R402H16]  67.06 91.97 270 top
R5505  10KR2J-3-GP  [R402H16]  138.68 96.92 270 bottom
R5506  100R2J-2-GP  [R402H14]  98.04 103.78 180 top
R5507  100KR2J-1-GP  [R402H16]  136.7 93.75 270 bottom
R5508  0R5J-5-GP  [R805H24]  71.88 92.6 90 top
R5509  0R5J-5-GP  [R805H24]  54.48 92.6 270 top
R5510  0R0402-PAD-2-GP  [0R0402-PAD-1]  106.68 100.98 270 top
R5511  0R0603-PAD-2-GP-U  [0R0603-PAD-1-U]  110.62 102.51 0 top
R5512  0R0805-PAD-2-GP-U  [0R0805-PAD-1-U]  53.34 90.16 90 top
R5515  0R3J-0-U-GP  [R603H22]  57.66 94.25 90 top
R5517  4K7R2J-2-GP  [R402H16]  69.98 93.24 180 top
R5518  4K7R2J-2-GP  [R402H16]  67.56 93.24 180 top
R5521  0R2J-L-GP  [R402H15]  69.22 93.24 180 top
R5522  0R2J-L-GP  [R402H15]  68.38 93.26 180 top
R5523  0R2J-L-GP  [R402H15]  138.68 97.68 90 bottom
R5524  0R2J-L-GP  [R402H15]  63.75 92.6 180 top
R5541  31K6R2F-GP  [R402H16]  52.2 92.6 270 top
R5542  10KR2F-2-DL-GP  [R402H16]  50.22 90.39 0 top
R5543  100R2J-2-GP  [R402H14]  86.87 103.78 180 top
R5544  100R2J-2-GP  [R402H14]  98.81 103.78 180 top
R5545  100R2J-2-GP  [R402H14]  100.66 103.37 270 top
R5546  0R0805-PAD-2-GP-U  [0R0805-PAD-1-U]  116.84 103.35 0 bottom
R5701  0R0603-PAD-2-GP-U  [0R0603-PAD-1-U]  26.16 42.31 0 bottom
R5702  100KR2J-1-GP  [R402H16]  27.05 73.68 0 bottom
R5703  0R2J-L-GP  [R402H15]  24.38 62.38 270 bottom
R5704  0R0402-PAD-2-GP  [0R0402-PAD-1]  32.82 64.13 0 top
R5705  0R2J-L-GP  [R402H15]  31.37 62.12 0 bottom
R5706  0R2J-L-GP  [R402H15]  30.23 54.88 0 top
R5707  0R0402-PAD-2-GP  [0R0402-PAD-1]  31.75 54.88 0 top
R5708  27KR2J-L1-GP  [R402H16]  27.05 50.44 90 bottom
R5709  0R2J-L-GP  [R402H15]  34.19 61 180 top
R5734  4D3KR2F-GP  [R402H16]  32.64 65.8 180 top
R5736  10KR2J-3-GP  [R402H16]  24.38 63.14 270 bottom
R5737  10KR2J-3-GP  [R402H16]  29.84 58.18 270 bottom
R5738  4K7R2J-2-GP  [R402H16]  29.72 59.45 0 bottom
R5739  4K7R2J-2-GP  [R402H16]  30.48 59.45 0 bottom
R5740  4K7R2J-2-GP  [R402H16]  20.19 55.39 0 bottom
R5741  10KR2J-3-GP  [R402H16]  23.88 56.66 270 bottom
R5742  4K7R2J-2-GP  [R402H16]  22.1 48.66 180 bottom
R5743  4K7R2J-2-GP  [R402H16]  23.88 48.53 180 bottom
R5744  10KR2J-3-GP  [R402H16]  23.11 51.07 90 top
R5747  10KR2J-3-GP  [R402H16]  20.57 57.8 180 bottom
R5748  1K5R2F-2-GP  [R402H16]  30.23 55.9 90 bottom
R5749  0R2J-L-GP  [R402H15]  14.73 57.04 270 bottom
R5750  1MR2J-1-GP  [R402H16]  31.88 55.9 90 bottom
R5751  2K2R2J-2-GP  [R402H16]  17.91 62.63 90 bottom
R5752  1MR2J-1-GP  [R402H16]  26.42 52.34 270 top
R5755  2K2R2J-2-GP  [R402H16]  17.91 63.39 90 bottom
R5756  4K7R2J-2-GP  [R402H16]  28.19 54.25 270 bottom
R5757  4K7R2J-2-GP  [R402H16]  33.02 55.26 270 top
R5760  1KR2F-3-GP  [R402H16]  26.54 70 0 top
R5761  0R2J-L-GP  [R402H15]  21.08 59.2 90 bottom
R5762  68R2F-GP  [R402H16]  34.8 67.2 90 top
R5763  68R2F-GP  [R402H16]  33.02 67.2 270 top
R5764  100KR2J-1-GP  [R402H16]  14.35 62.25 0 bottom
R5765  5D1R2F-GP  [R402H16]  25.15 53.74 270 top
R5766  5D1R2F-GP  [R402H16]  25.15 54.5 270 top
R5767  5D1R2F-GP  [R402H16]  19.94 61.99 180 top
R5768  5D1R2F-GP  [R402H16]  20.7 61.99 180 top
R5769  5D1R2F-GP  [R402H16]  20.32 63.9 270 top
R5770  5D1R2F-GP  [R402H16]  20.32 64.66 270 top
R5771  5D1R2F-GP  [R402H16]  20.32 65.42 270 top
R5772  5D1R2F-GP  [R402H16]  20.32 66.19 270 top
R5773  5K1R2F-2-GP  [R402H16]  24.64 41.04 180 bottom
R5774  10KR2F-2-DL-GP  [R402H16]  24.26 39.77 90 bottom
R5775  0R0402-PAD-2-GP  [0R0402-PAD-1]  28.45 30.88 180 bottom
R6101  D01R5F-GP  [R805H24]  178 34.05 180 top
R6106  10KR2J-3-GP  [R402H16]  179.83 38.12 90 top
R6107  0R2J-L-GP  [R402H15]  180.21 36.85 180 top
R6108  0R2J-L-GP  [R402H15]  182.88 36.85 180 top
R6109  10KR2J-3-GP  [R402H16]  180.37 35.5 90 top
R6110  0R2J-L-GP  [R402H15]  185.55 43.81 180 top
R6111  10KR2J-3-GP  [R402H16]  179.43 42.66 180 top
R6112  20KR2J-L2-GP  [R402H16]  179.07 43.83 270 top
R6113  0R0603-PAD-2-GP-U  [0R0603-PAD-1-U]  178.36 39.16 90 top
R6301  0R0402-PAD-2-GP  [0R0402-PAD-1]  169.54 9.29 90 top
R6302  0R0603-PAD-2-GP-U  [0R0603-PAD-1-U]  148.41 8.37 0 bottom
R6303  10KR2J-3-GP  [R402H16]  169.54 10.81 270 top
R6304  10KR2J-3-GP  [R402H16]  169.54 10.05 90 top
R6305  100KR2J-1-GP  [R402H16]  167.51 7.13 90 top
R6306  0R0603-PAD-2-GP-U  [0R0603-PAD-1-U]  146.56 8.93 270 bottom
R6307  10KR2J-3-GP  [R402H16]  166.88 4.72 270 top
R6308  0R2J-L-GP  [R402H15]  166.88 5.48 90 top
R6401  499R2F-2-GP  [R402H16]  114.17 14.24 90 bottom
R6402  330R2J-3-GP  [R402H16]  114.17 16.15 90 bottom
R6405  10KR2J-3-GP  [R402H16]  133.07 8.4 270 bottom
R6406  10KR2J-3-GP  [R402H16]  126.24 14.12 0 bottom
R6419  0R2J-L-GP  [R402H15]  121.89 7.1 90 bottom
R6420  0R2J-L-GP  [R402H15]  127 14.12 0 bottom
R6421  0R0402-PAD-2-GP  [0R0402-PAD-1]  121.67 8.91 270 bottom
R6422  0R0402-PAD-2-GP  [0R0402-PAD-1]  121.34 12.57 270 bottom
R6502  0R3J-0-U-GP  [R603H22]  132.33 8.15 180 top
R6503  100R3J-4-GP  [R603H22]  130.43 8.15 0 top
R6504  20KR2F-L-GP  [R402H16]  127.38 12.72 270 bottom
R6505  0R2J-L-GP  [R402H15]  135.38 10.81 90 top
R6506  0R2J-L-GP  [R402H15]  135.38 10.05 90 top
R6507  51KR2J-1-GP  [R402H16]  76.45 17.04 180 top
R6508  100KR2J-1-GP  [R402H16]  76.71 15.77 90 top
R6509  100KR2J-1-GP  [R402H16]  77.09 16.66 0 bottom
R6510  0R0402-PAD-2-GP  [0R0402-PAD-1]  135.33 11.63 270 bottom
R6511  10KR2J-3-GP  [R402H16]  139.45 9.87 0 top
R6512  0R0402-PAD-2-GP  [0R0402-PAD-1]  67.31 11.45 180 bottom
R6513  1KR2J-1-GP  [R402H16]  61.34 12.85 90 bottom
R6801  0R2J-L-GP  [R402H15]  92.58 13.23 270 top
R6802  0R2J-L-GP  [R402H15]  90.81 13.23 270 top
R6803  0R2J-L-GP  [R402H15]  87.12 19.04 270 top
R7001  0R3J-0-U-GP  [R603H22]  178.69 48.28 0 top
R7002  10KR2J-3-GP  [R402H16]  187.07 36.85 180 top
R7003  0R2J-L-GP  [R402H15]  187.83 36.85 180 top
R7004  10KR2J-3-GP  [R402H16]  186.31 36.85 0 top
R7005  0R2J-L-GP  [R402H15]  181.61 38.88 90 top
R7006  0R2J-L-GP  [R402H15]  183.9 39.9 90 top
R7007  0R2J-L-GP  [R402H15]  183.9 39.13 90 top
R7008  0R2J-L-GP  [R402H15]  184.78 43.83 0 top
R7101  100KR2J-1-GP  [R402H16]  35.94 85.62 0 bottom
R7102  100KR2J-1-GP  [R402H16]  38.23 85.24 0 bottom
R7114  0R0402-PAD-2-GP  [0R0402-PAD-1]  41.53 85.36 180 bottom
R7115  0R0402-PAD-2-GP  [0R0402-PAD-1]  20.17 80.08 0 top
R7116  0R0402-PAD-2-GP  [0R0402-PAD-1]  40.77 85.36 180 bottom
R7117  0R0402-PAD-2-GP  [0R0402-PAD-1]  19.41 80.08 0 top
R7118  10KR2J-3-GP  [R402H16]  33.53 88.79 90 top
R7119  0R0402-PAD-2-GP  [0R0402-PAD-1]  18.03 76.47 270 top
R7120  0R0402-PAD-2-GP  [0R0402-PAD-1]  18.03 77.23 270 top
R7121  4K7R2J-2-GP  [R402H16]  33.53 89.55 90 top
R7122  0R0402-PAD-2-GP  [0R0402-PAD-1]  17.02 90.7 270 top
R7123  0R0402-PAD-2-GP  [0R0402-PAD-1]  17.02 89.93 270 top
R7124  0R0402-PAD-2-GP  [0R0402-PAD-1]  17.02 89.17 270 top
R7125  0R0402-PAD-2-GP  [0R0402-PAD-1]  17.02 88.41 270 top
R7140  1KR2J-1-GP  [R402H16]  33.53 90.32 90 top
R7141  1KR2J-1-GP  [R402H16]  36.32 90.32 90 top
R7142  1KR2J-1-GP  [R402H16]  33.53 91.08 90 top
R7143  1KR2J-1-GP  [R402H16]  36.45 92.73 90 top
R7144  1KR2J-1-GP  [R402H16]  37.59 94.25 90 top
R7145  1KR2J-1-GP  [R402H16]  41.91 93.74 270 top
R7146  1KR2J-1-GP  [R402H16]  39.5 93.74 270 top
R7147  1KR2J-1-GP  [R402H16]  34.67 93.49 90 top
R7149  0R0402-PAD-2-GP  [0R0402-PAD-1]  39.5 85.11 270 bottom
R7151  0R0402-PAD-2-GP  [0R0402-PAD-1]  34.04 86 90 bottom
R7152  1KR2J-1-GP  [R402H16]  37.34 95.52 0 top
R7153  0R0402-PAD-2-GP  [0R0402-PAD-1]  34.04 86.76 90 bottom
R7170  1KR2J-1-GP  [R402H16]  36.45 93.49 90 top
R7171  1KR2J-1-GP  [R402H16]  41.91 91.97 270 top
R7172  1KR2J-1-GP  [R402H16]  39.5 91.97 270 top
R7173  1KR2J-1-GP  [R402H16]  39.5 90.19 270 top
R7174  1KR2J-1-GP  [R402H16]  41.91 90.19 270 top
R7201  0R0402-PAD-2-GP  [0R0402-PAD-1]  11.68 80.92 270 bottom
R7202  100KR2J-1-GP  [R402H16]  17.27 81.55 180 top
R7204  0R2J-2-GP  [R402H16]  24.13 84.09 270 top
R7206  15KR2F-GP  [R402H16]  11.68 82.44 90 bottom
R7208  1MR2J-1-GP  [R402H16]  24.13 82.57 270 top
R7209  1MR2J-1-GP  [R402H16]  11.73 79.37 270 bottom
R7211  0R0402-PAD-2-GP  [0R0402-PAD-1]  20.35 86.53 180 top
R7212  0R0402-PAD-2-GP  [0R0402-PAD-1]  22.28 86.53 180 top
R7213  1MR2J-1-GP  [R402H16]  24.13 81.81 270 top
R7214  1MR2J-1-GP  [R402H16]  24.13 81.04 270 top
R7215  100KR2F-L1-GP  [R402H16]  16.64 72.03 0 top
R7216  0R0402-PAD-2-GP  [0R0402-PAD-1]  18.67 73.55 0 bottom
R7217  0R0402-PAD-2-GP  [0R0402-PAD-1]  17.91 73.55 0 bottom
R7218  0R2J-2-GP  [R402H16]  17.53 73.81 0 top
R7219  0R2J-2-GP  [R402H16]  18.29 73.81 0 top
R7220  0R0402-PAD-2-GP  [0R0402-PAD-1]  14.35 88.03 180 bottom
R7221  0R0402-PAD-2-GP  [0R0402-PAD-1]  13.59 88.03 180 bottom
R7222  10KR2J-3-GP  [R402H16]  15.24 84.22 90 top
R7223  43KR2F-GP  [R402H16]  17.02 84.22 90 top
R7224  10KR2J-3-GP  [R402H16]  11.71 77.82 270 bottom
R7225  3K3R2J-3-GP  [R402H16]  20.19 50.69 0 bottom
R7226  3K3R2J-3-GP  [R402H16]  17.53 57.93 180 bottom
R7227  0R0402-PAD-2-GP  [0R0402-PAD-1]  39.5 84.35 90 bottom
R7228  3K3R2J-3-GP  [R402H16]  20.19 52.47 0 bottom
R7229  0R0402-PAD-2-GP  [0R0402-PAD-1]  25.91 82.82 90 top
R7230  3K3R2J-3-GP  [R402H16]  13.21 51.2 90 bottom
R7231  1MR2J-1-GP  [R402H16]  18.03 81.55 0 top
R7235  0R0402-PAD-2-GP  [0R0402-PAD-1]  16.64 73.81 180 top
R7236  0R0402-PAD-2-GP  [0R0402-PAD-1]  24.13 83.33 90 top
R7237  1MR2J-1-GP  [R402H16]  16.64 88.03 180 bottom
R7238  100KR2J-1-GP  [R402H16]  11.68 85.24 270 bottom
R7239  100KR2J-1-GP  [R402H16]  11.68 84.47 270 bottom
R7241  1MR2J-1-GP  [R402H16]  15.11 88.03 180 bottom
R7242  1MR2J-1-GP  [R402H16]  15.88 88.03 180 bottom
R7243  10KR2J-3-GP  [R402H16]  11.71 78.58 270 bottom
R7244  100KR2J-1-GP  [R402H16]  11.68 81.68 270 bottom
R7330  2MR2F-GP  [R402H16]  34.04 87.52 270 bottom
R7331  2MR2F-GP  [R402H16]  34.04 85.24 270 bottom
R7401  100KR2J-1-GP  [R402H16]  97.79 23.26 270 bottom
R7402  200KR2F-L-GP  [R402H16]  25.15 70.12 90 top
R7403  0R0402-PAD-2-GP  [0R0402-PAD-1]  25.2 69.31 90 top
R7404  1MR2J-1-GP  [R402H16]  24.51 67.96 180 top
R7405  100KR2J-1-GP  [R402H16]  15.62 68.85 180 top
R7406  100KR2J-1-GP  [R402H16]  22.73 66.95 270 top
R7407  200KR2F-L-GP  [R402H16]  17.65 67.46 270 top
R7408  200KR2F-L-GP  [R402H16]  17.27 68.73 0 top
R7409  200KR2F-L-GP  [R402H16]  20.83 69.49 180 top
R7410  100KR2J-1-GP  [R402H16]  28.07 69.23 0 bottom
R7411  1MR2J-1-GP  [R402H16]  24.64 66.06 180 bottom
R7422  1MR2J-1-GP  [R402H16]  22.35 70 180 top
R7423  100KR2J-1-GP  [R402H16]  18.29 70.25 0 top
R7424  100KR2J-1-GP  [R402H16]  23.11 70 0 top
R7425  100KR2J-1-GP  [R402H16]  19.94 70.25 0 top
R7426  100KR2J-1-GP  [R402H16]  19.18 70.25 0 top
R7427  100KR2J-1-GP  [R402H16]  23.88 70 0 top
R9126  0R3J-0-U-GP  [R603H22]  163.96 52.47 90 bottom
R9127  0R3J-0-U-GP  [R603H22]  163.96 51.2 90 bottom
R9130  0R2J-2-GP  [R402H16]  160.27 53.99 0 bottom
R9132  33R2J-2-GP  [R402H16]  135.02 59.39 0 bottom
R9133  33R2J-2-GP  [R402H16]  134.59 62.97 180 bottom
R9136  0R2J-2-GP  [R402H16]  167 60.98 90 bottom
R9137  0R2J-2-GP  [R402H16]  167 59.45 270 bottom
R9138  33R2J-2-GP  [R402H16]  135.65 62.97 180 bottom
R9139  0R2J-2-GP  [R402H16]  167 60.22 90 bottom
R9140  10KR2J-3-GP  [R402H16]  162.31 54.5 90 bottom
R9141  0R2J-2-GP  [R402H16]  159.26 54.25 180 bottom
R9143  0R3J-0-U-GP  [R603H22]  156.41 56.15 0 bottom
R9148  10KR2J-3-GP  [R402H16]  161.04 53.99 0 bottom
R9149  10KR2J-3-GP  [R402H16]  164.72 55.29 90 bottom
R9209  0R0402-PAD-2-GP  [0R0402-PAD-1]  169.24 50.06 270 bottom
R9210  0R0402-PAD-2-GP  [0R0402-PAD-1]  169.24 49.29 270 bottom
R9211  0R0603-PAD-2-GP-U  [0R0603-PAD-1-U]  177.42 49.55 180 top
R9804  4K7R2F-GP  [R402H16]  36.45 13.35 270 bottom
R9805  1KR2F-3-GP  [R402H16]  36.45 14.12 90 bottom
R9806  0R0402-PAD-2-GP  [0R0402-PAD-1]  36.07 7.13 270 bottom
RAM1  MT40A256M16GE-083E-B-COLAY1-GP  [BGA96D0914H48-COLAY-4]  85.58 39.34 180 bottom
RAM2  MT40A256M16GE-083E-B-COLAY1-GP  [BGA96D0914H48-COLAY-4]  75.43 39.34 180 bottom
RAM3  MT40A256M16GE-083E-B-COLAY1-GP  [BGA96D0914H48-COLAY-4]  65.28 39.34 180 bottom
RAM4  MT40A256M16GE-083E-B-COLAY1-GP  [BGA96D0914H48-COLAY-4]  55.13 39.34 180 bottom
RAM5  MT40A256M16GE-083E-B-COLAY1-GP  [BGA96D0914H48-COLAY-4]  117.78 39.34 180 bottom
RAM6  MT40A256M16GE-083E-B-COLAY1-GP  [BGA96D0914H48-COLAY-4]  107.63 39.34 180 bottom
RAM7  MT40A256M16GE-083E-B-COLAY1-GP  [BGA96D0914H48-COLAY-4]  138.08 39.34 180 bottom
RAM8  MT40A256M16GE-083E-B-COLAY1-GP  [BGA96D0914H48-COLAY-4]  127.93 39.34 180 bottom
RN401  SRN2K2J-1-GP  [ARES2H16]  126.95 86 180 top
RN403  SRN2K2J-1-GP  [ARES2H16]  131.62 95.02 0 bottom
RN1202  SRN36J-GP  [ARES8-CN24-UH20]  47.92 38.13 90 top
RN1203  SRN36J-GP  [ARES8-CN24-UH20]  44.49 32.41 90 top
RN1204  SRN36J-GP  [ARES8-CN24-UH20]  47.92 32.41 90 top
RN1205  SRN36J-GP  [ARES8-CN24-UH20]  47.92 34.82 90 top
RN1206  SRN36J-GP  [ARES8-CN24-UH20]  44.49 34.82 90 top
RN1207  SRN36J-GP  [ARES8-CN24-UH20]  44.49 37.24 90 top
RN1302  SRN36J-GP  [ARES8-CN24-UH20]  145.46 39.14 90 bottom
RN1303  SRN36J-GP  [ARES8-CN24-UH20]  145.9 35.58 90 top
RN1304  SRN36J-GP  [ARES8-CN24-UH20]  145.52 33.17 90 bottom
RN1305  SRN36J-GP  [ARES8-CN24-UH20]  145.87 38.04 90 top
RN1306  SRN36J-GP  [ARES8-CN24-UH20]  145.52 35.59 90 bottom
RN1307  SRN36J-GP  [ARES8-CN24-UH20]  145.9 33.17 90 top
RN1601  SRN10KJ-6-GP  [ARES8-CN24-MUH20]  137.05 85.93 90 top
RN1602  SRN100KJ-6-GP  [SMD-ARES4]  152.12 91.48 0 top
RN1701  SRN10KJ-5-GP  [ARES2H18]  127.13 62.5 180 bottom
RN1703  SRN10KJ-5-GP  [ARES2H18]  124.33 58.82 180 bottom
RN1801  SRN20KJ-1-GP  [SMD-ARES4H20]  138.3 51.07 270 bottom
RN1802  SRN10KJ-5-GP  [ARES2H18]  144.15 59.45 90 top
RN1806  SRN15J-GP  [ARES8-CN24-MUH20]  131.85 60.17 0 top
RN1807  SRN2K2J-4-GP  [ARES8-CN24-UH20]  135.51 82.44 90 top
RN1811  SRN2K2J-1-GP  [ARES2H16]  139.06 81.17 0 top
RN1813  SRN10KJ-6-GP  [ARES8-CN24-MUH20]  144.15 57.42 90 top
RN2007  SRN1KJ-7-GP  [SMD-ARES4H18]  137.48 78.69 180 top
RN2008  SRN2K2J-1-GP  [ARES2H16]  134.9 77.51 270 top
RN2402  SRN4K7J-8-GP  [SMD-ARES4H18]  80.39 11.32 90 bottom
RN2403  SRN10KJ-6-GP  [ARES8-CN24-MUH20]  41.02 3.37 0 top
RN2404  SRN10KJ-6-GP  [ARES8-CN24-MUH20]  44.83 3.32 0 top
RN2405  SRN100KJ-5-GP  [ARES8-CN24H20]  123.4 11.32 0 top
RN2409  SRN100KJ-5-GP  [ARES8-CN24H20]  49.15 3.32 0 top
RN2410  SRN100KJ-5-GP  [ARES8-CN24H20]  60.07 3.32 0 top
RN2411  SRN100KJ-5-GP  [ARES8-CN24H20]  56.26 3.32 0 top
RN2412  SRN100KJ-5-GP  [ARES8-CN24H20]  52.7 3.32 0 top
RN2413  SRN2K2J-1-GP  [ARES2H16]  103.25 11.83 270 bottom
RN2602  SRN2K2J-1-GP  [ARES2H16]  41.27 13.43 90 bottom
RN2702  SRN1KJ-7-GP  [SMD-ARES4H18]  9.91 4.84 270 bottom
RN2703  SRN2K2J-1-GP  [ARES2H16]  29.74 15.46 270 bottom
RN2901  SRN2K2J-1-GP  [ARES2H16]  17.4 19.83 90 top
RN4302  SRN100J-3-GP  [SMD-ARES4H18]  163.65 28.29 270 bottom
RN5502  SRN100KJ-5-GP  [ARES8-CN24H20]  99.31 101.75 0 top
RN5503  SRN33J-5-GP-U  [SMD-ARES4H18]  109.22 102.13 0 top
RN5504  SRN33J-5-GP-U  [SMD-ARES4H18]  116.2 99.33 270 top
RN6501  SRN10KJ-5-GP  [ARES2H18]  141.1 10.05 270 top
RN6502  SRN33J-5-GP-U  [SMD-ARES4H18]  146.3 9.92 270 top
RN6503  SRN2K2J-1-GP  [ARES2H16]  135.38 10.43 90 bottom
RN7202  SRN10KJ-5-GP  [ARES2H18]  14.66 80.28 0 top
RN7206  SRN2K2J-1-GP  [ARES2H16]  14.61 82.7 180 top
SPK1  ACES-CON8-13-GP-U2  [50224-0080N-W02-U]  19.55 3.7 180 bottom
SPR1  SPRING-31-GP-U  [SPR6035H166]  94.8 51.9 0 bottom
SPR2  SPRING-31-GP-U  [SPR6035H166]  71.8 26.7 0 bottom
SSD1  SKT-MINI67P-43-GP  [APCI0181-P001A]  174.95 14.6 270 bottom
TCBD1  HRS-CON20-12-GP  [TF31-20S-0D5SH-800]  66.05 93.3 180 bottom
TP1  PTWO-CON8-16-GP  [196574-08021-3]  141.35 5.2 180 bottom
TP301  TPAD14-OP-GP  [TPAD14-OP]  100.2 96.41 180 bottom
TP302  TPAD14-OP-GP  [TPAD14-OP]  95.89 94.76 180 bottom
TP303  TPAD14-OP-GP  [TPAD14-OP]  97.05 94.3 180 bottom
TP304  TPAD14-OP-GP  [TPAD14-OP]  97.61 95.4 180 bottom
TP305  TPAD14-OP-GP  [TPAD14-OP]  99.31 93.11 180 bottom
TP306  TPAD14-OP-GP  [TPAD14-OP]  98.3 94.38 180 bottom
TP307  TPAD14-OP-GP  [TPAD14-OP]  96.8 93.08 180 bottom
TP308  TPAD14-OP-GP  [TPAD14-OP]  130.81 84.47 0 top
TP309  TPAD14-OP-GP  [TPAD14-OP]  118.49 95.65 180 bottom
TP311  TPAD14-OP-GP  [TPAD14-OP]  92.79 94.25 180 bottom
TP313  TPAD14-OP-GP  [TPAD14-OP]  90.3 93.62 180 bottom
TP314  TPAD14-OP-GP  [TPAD14-OP]  103.1 87.27 0 top
TP315  TPAD14-OP-GP  [TPAD14-OP]  101.85 87.52 0 top
TP402  TPAD14-OP-GP  [TPAD14-OP]  137.92 94.63 180 bottom
TP618  TPAD14-OP-GP  [TPAD14-OP]  98.04 93.11 180 bottom
TP619  TPAD14-OP-GP  [TPAD14-OP]  87.88 88.54 180 bottom
TP620  TPAD14-OP-GP  [TPAD14-OP]  135.35 71.22 0 top
TP1201  TPAD14-OP-GP  [TPAD14-OP]  50.34 34.19 0 top
TP1202  TPAD14-OP-GP  [TPAD14-OP]  80.87 34.47 0 top
TP1203  TPAD14-OP-GP  [TPAD14-OP]  60.27 34.97 0 top
TP1204  TPAD14-OP-GP  [TPAD14-OP]  70.72 34.47 0 top
TP1301  TPAD14-OP-GP  [TPAD14-OP]  102.18 35.98 0 top
TP1302  TPAD14-OP-GP  [TPAD14-OP]  123.85 34.44 0 top
TP1303  TPAD14-OP-GP  [TPAD14-OP]  113.71 34.47 0 top
TP1304  TPAD14-OP-GP  [TPAD14-OP]  134 34.47 0 top
TP1708  TPAD14-OP-GP  [TPAD14-OP]  131.19 64.28 180 bottom
TP1804  TPAD14-OP-GP  [TPAD14-OP]  130.71 77.01 90 top
TP1806  TPAD14-OP-GP  [TPAD14-OP]  131.22 78.12 90 top
TP1807  TPAD14-OP-GP  [TPAD14-OP]  113.41 94.38 180 bottom
TP1808  TPAD14-OP-GP  [TPAD14-OP]  113.41 93.11 180 bottom
TP1903  TPAD14-OP-GP  [TPAD14-OP]  122.02 64.71 180 bottom
TP2201  TPAD14-OP-GP  [TPAD14-OP]  129.92 64.66 180 bottom
TP2202  TPAD14-OP-GP  [TPAD14-OP]  130.56 63.14 180 bottom
TP2402  TPAD14-OP-GP  [TPAD14-OP]  85.37 18.53 0 top
TP4401  TPAD28-2-GP  [TPAD28]  33.73 50.54 270 top
TP4601  TPAD14-OP-GP  [TPAD14-OP]  48.01 82.31 0 bottom
TP7202  TPAD14-OP-GP  [TPAD14-OP]  15.62 85.62 0 bottom
TP7203  TPAD14-OP-GP  [TPAD14-OP]  19.56 85.36 0 bottom
TP7204  TPAD14-OP-GP  [TPAD14-OP]  18.44 88.13 0 bottom
TP7205  TPAD14-OP-GP  [TPAD14-OP]  27.81 83.97 180 top
TP8304  TPAD14-OP-GP  [TPAD14-OP]  33.02 43.2 180 top
TP9101  TPAD14-OP-GP  [TPAD14-OP]  158.62 58.06 180 bottom
TP9102  TPAD14-OP-GP  [TPAD14-OP]  158.62 59.33 180 bottom
TP9103  TPAD14-OP-GP  [TPAD14-OP]  156.84 54.25 180 bottom
TP9104  TPAD14-OP-GP  [TPAD14-OP]  163.96 63.26 180 bottom
U2401  MEC1416-NU-D0-GP  [TQFP128-2H48]  91.31 14.29 270 bottom
U2502  G517F1T12U-GP  [SOT-23-5H58]  153.59 73.05 90 bottom
U2601  NCT7718W-GP  [MSOP8-1H44]  152.02 44.98 180 bottom
U2701  ALC3254-VA3-CG-GP  [QFN48J6-G465H40]  23.62 18.43 270 top
U3401  TPS2544RTER-GP  [QFN16-G1D8-UH32]  20.32 43.07 90 bottom
U4001  TPS22976DPUR-GP  [SON14J3020-G2610H34]  105.99 24.76 0 bottom
U4002  G5027RD1D-GP-U  [DFN8F3-G2517H32]  152.65 61.74 180 bottom
U4003  G5027RD1D-GP-U  [DFN8F3-G2517H32]  159.77 67.2 180 bottom
U4006  G5027RD1D-GP-U  [DFN8F3-G2517H32]  149.1 97.43 0 bottom
U4008  TC7SZ08FU-LJ-CT-GP  [SC70-5H44]  156.44 61.25 0 bottom
U4302  S-1004NA23I-M5T1U-GP  [SOT-23-5H52]  34.67 56.55 180 bottom
U5501  G517F1T12U-GP  [SOT-23-5H58]  121.03 103.52 180 bottom
U5503  APL5324BI-TRG-GP  [SOT-23-5H58]  50.8 91.46 180 bottom
U5504  L05ESDL5V0NA-4-GP  [SLP2510P8-1H22]  85.72 101.75 180 top
U5701  PS175HDMBGA64GTR2-B2-GP  [BGA64D7H51]  27.18 61.49 0 top
U5702  MX25L2006EM1I-12G-GP-U  [SOIC8H69]  23.37 52.85 0 bottom
U5704  APL5934KAI-TRG-GP-U  [SOIC8-G3530H63]  26.04 35.96 0 bottom
U6402  74LVC1G08GW-1-GP  [SC70-5H44]  122.3 4.97 0 bottom
U7001  LNG2DMTR-GP  [LGA12G2H40]  186.21 39.52 180 top
U7101  TUSB546-DCIRNQR-1-GP  [QFN40J4060-G2848H32]  37.97 91.08 180 bottom
U7201  SN1703018ZQZR-GP  [BGA96G60-1H40]  17.27 81.17 0 bottom
U7202  W25Q80DVSNIG-GP-U  [SOIC8H69]  17.02 52.98 180 bottom
U7418  AON7403-GP-U  [PPAK-8P-3232H36]  25.78 70 180 bottom
U7419  NX20P5090UK-GP  [CSP15G154256H24]  22.86 69.87 0 bottom
U9102  NPCT750JAAYX-GP  [QFN32G5-G3D6H32]  162.27 59.06 270 bottom
USB1  SKT-USB36-20-GP  [SKT-USB36-124102-1]  2.25 81.3 90 bottom
USB2  SKT-USB13-18-GP-U  [SKT-USB13-160166-2]  6.45 41 90 bottom
X1801  XTAL-24MHZ-182-GP  [OSC-3225-4P-3H36]  135.51 97.81 0 bottom
X1802  XTAL-32D768KHZ-98-GP  [SMD49-12H34]  123.34 56.11 90 top
X2401  XTAL-32D768KHZ-98-GP  [SMD49-12H34]  83.44 4.21 90 bottom
X5701  XTAL-27MHZ-192-GP  [SMD-OSC38H32]  31.11 52.98 180 bottom

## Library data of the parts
AFTP2601-AFTP2604 AFTP2901-AFTP2904 AFTP4301-AFTP4316 AFTP5701 AFTP6108-AFTP6114 AFTP6301 AFTP6303 AFTP6304 AFTP6501-AFTP6525 AFTP6529-AFTP6539 AFTP6607-AFTP6609 = AFTE14P-75: tolerance: ZZ.AFT14.101
BATT1 = A2014WRA-SF-10PNLNG1NS1R: tolerance: 020.F0867.0010
BIOS1 = SOIC8-1H86: tolerance: 072.25128.0B51
C501 C805 C1139-C1142 C2206 C2207 C2221 C2406-C2408 C2410-C2414 C2416 C2420-C2423 C2428 C2429 C2602 C2605 C2612 C2714 C2721 C2722 C2726 C2729 C2740 C2742 C2744 C3402 C3403 C4010 C4034 C4037 C4040 C5507 C5726 C5736 C5744 C5750-C5752 C5755 C5756 C5761 C5765-C5767 C5773 C5774 C6105 C6106 C6307 C6501 C6502 C6505 C6702 C7002 C7115-C7118 C7302-C7304 C7307 EC2201 EC2402 EC2403 EC2712-EC2714 EC3501 EC4302 EC4311 EC4313 EC4701 EC5001 EC8901-EC8904 EC8906-EC8934 EC8937-EC8950 PC4406 PC4501 PC4506 PC4508 PC4513 PC4521 PC4522 PC4528 PC4530-PC4532 PC4543 PC4602 PC4603 PC4631 PC4633 PC5004 PC5114 PC5116 PC5118 PC5123 PC5204 PC5208 PC5214 PC5327 = C402H22: tolerance: 78.10422.5FLDL
C801-C804 C806 C1102-C1111 C1114 C1116 C1117 C1119 C1121 C1204-C1235 C1255 C1257-C1274 C1280-C1284 C1292-C1299 C1304-C1335 C1337-C1342 C1344-C1369 C1805 C1806 C2202-C2205 C2209-C2217 C2219 C2222-C2224 C2418 C2525 C3401 C4031 C4032 C4035 C4038 C4043 C5508 C5535 C5725 C5743 C7210 C9201 EC8905 PC4425 PC4607 PC4708 PC4766 PC4809 PC4812 PC4866 PC4877 PC5110 PC5121 PC5202 PC5301 PC5310 = C402H22: tolerance: 78.10523.5FLDL
C1112 C1113 C1115 C1118 C1122 C1128-C1135 C2208 C2220 C3404 C3405 C4041 C4042 C5505 C6317 C6318 C7204 C7205 PC1001-PC1032 PC1034 PC1036-PC1084 PC4509-PC4512 PC4514-PC4517 PC4525 PC4527 PC4529 PC4542 PC5104 PC5105 PC5107 PC5109 PC5124 PC5201 PC5203 PC5205 PC5206 PC5304 PC5312 = C603H40: tolerance: 78.22610.5BLDL
C1120 C1123 C1136-C1138 C1237-C1246 C1275-C1279 C1288-C1291 C1371-C1379 C1390-C1399 C2501 C2601 C2727 C2730 C2732 C2733 C2745 C2907-C2909 C4006 C4008 C4009 C4012 C4013 C5517 C5518 C5742 C5746 C5747 C5749 C6104 C7001 C7119 C7211 C9106 C9109 PC5122 PC5302 PC5303 PC5313 PC5314 = C603H36: tolerance: 78.10610.5BLDL
C1201 C1203 C1236 C1286 C1301 C1303 C1336 C1343 C6306 C6308 C6701 PC4605 PC4630 PC4634 PC4653 = C402H22: tolerance: 078.47322.02FD
